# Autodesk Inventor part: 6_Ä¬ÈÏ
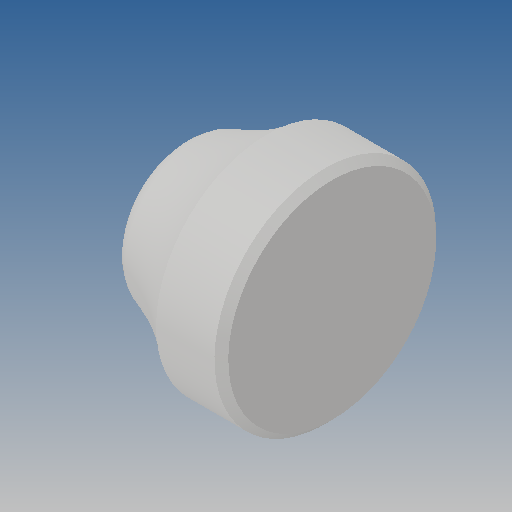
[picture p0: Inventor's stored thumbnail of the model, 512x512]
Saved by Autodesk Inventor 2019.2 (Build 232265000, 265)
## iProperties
Created: 2010-06
Part Number: 6_Ä¬ÈÏ
Material: Ogólny
Document SubType Name: Modeling
Designer: CADENGINEERING4
Density: 1 g/cm^3
Appearance: Domyślna
Author: CADENGINEERING4
Revision Number: ÈÎºÎ
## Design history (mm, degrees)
feature "NONE"
node "Bryła1"
